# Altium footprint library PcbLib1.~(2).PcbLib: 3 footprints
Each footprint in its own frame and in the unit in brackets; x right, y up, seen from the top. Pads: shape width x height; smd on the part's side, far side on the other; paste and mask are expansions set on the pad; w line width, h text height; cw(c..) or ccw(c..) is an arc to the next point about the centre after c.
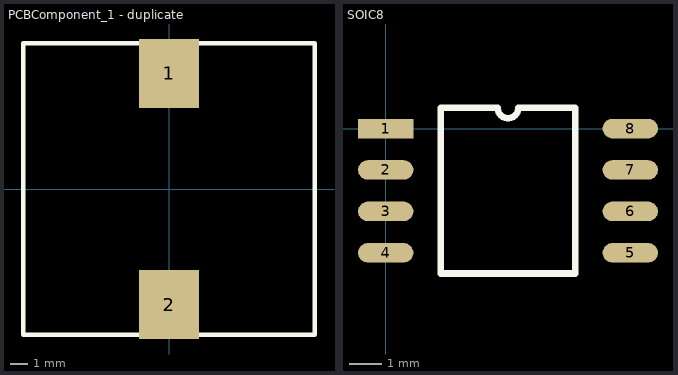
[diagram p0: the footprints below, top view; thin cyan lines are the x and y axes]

## PCBComponent_1 [mm]

## PCBComponent_1 - duplicate [mm]
pads (2):
  rect 3.5x4 smd: 1(0,6.7) 2(0,-6.7)
Top Overlay:
  lines w0.254: -8.45,-8.45 -8.45,8.45 8.45,8.45 8.45,-8.45 -8.45,-8.45

## SOIC8 [mm]
pads (8):
  rect 1.7x0.6 smd: 1(0,0)
  oval 1.7x0.6 smd: 2(0,-1.27) 3(0,-2.54) 4(0,-3.81) 5(7.5,-3.81) 6(7.5,-2.54) 7(7.5,-1.27) 8(7.5,0)
Top Overlay:
  lines w0.2: 1.685,-4.445 5.815,-4.445 5.815,0.635 4.068,0.635 cw(c3.75,0.635) 3.433,0.635 1.685,0.635 1.685,-4.445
